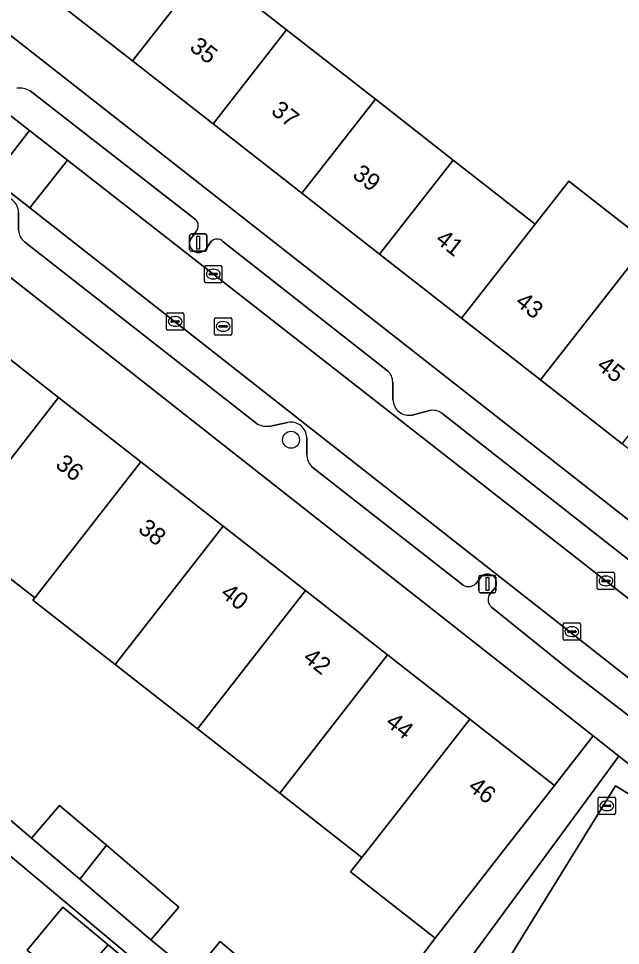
# Model space of a CAD drawing. Extents: x 162803 to 163818, y 381639 to 382475.
# Drawn here: x 163015.6 to 163050.3, y 381895.4 to 381948.9 of the extents above; entities that cross this region are included whole.
import ezdxf

# ---------------------------------------------------------------- set-up
doc = ezdxf.new("R2010")
doc.units = 0
for name, color, linetype in [('IMGEO_Boom', 7, 'Continuous'), ('IMGEO_Erf', 7, 'Continuous'), ('IMGEO_Hek', 7, 'Continuous'), ('IMGEO_Kolk', 7, 'Continuous'), ('IMGEO_Lichtmast', 7, 'Continuous'), ('IMGEO_Pand', 7, 'Continuous'), ('IMGEO_Pand_nummerreeks', 7, 'Continuous'), ('IMGEO_Parkeervlak_open', 7, 'Continuous'), ('IMGEO_Rijbaan_lokaal_open', 7, 'Continuous'), ('IMGEO_Rioolput', 7, 'Continuous'), ('IMGEO_Voetpad_halfverhard', 7, 'Continuous'), ('IMGEO_Voetpad_open', 7, 'Continuous')]:
    doc.layers.add(name, color=color, linetype=linetype)

msp = doc.modelspace()

# ---------------------------------------------------------------- linework, layer by layer
at = {"layer": 'IMGEO_Boom'}
msp.add_circle((163031.306, 381924.552), 0.489, dxfattribs=at)
at = {"layer": 'IMGEO_Erf'}
for points in [[(163012.702, 381953.831), (163008.064, 381957.46), (163003.34, 381961.156), (163000, 381963.77), (162998.624, 381964.847), (162993.983, 381968.479), (162988.995, 381972.382), (162984.262, 381976.085), (162979.885, 381979.51), (162977.939, 381977.029), (163000, 381959.74), (163053.051, 381918.164), (163055.049, 381920.693), (163050.42, 381924.316), (163045.704, 381928.006), (163041.156, 381931.565), (163036.417, 381935.273), (163031.932, 381938.782), (163026.803, 381942.796), (163022.156, 381946.432), (163017.462, 381950.105)], [(163001.097, 381944.923), (162998.748, 381941.944), (163000, 381940.965), (163003.631, 381938.127), (163008.381, 381934.414), (163013.132, 381930.701), (163017.883, 381926.987), (163022.634, 381923.274), (163027.384, 381919.561), (163032.135, 381915.847), (163036.886, 381912.134), (163041.636, 381908.421), (163046.521, 381904.603), (163048.763, 381907.455)], [(163038.651, 381883.086), (163036.828, 381884.162), (163039.676, 381888.972), (163040.229, 381888.673), (163050.041, 381904.572), (163054.928, 381901.596), (163055.361, 381902.269), (163050.243, 381906.292), (163034.914, 381885.439), (163037.605, 381883.275), (163019.349, 381863.218), (163031.785, 381852.208), (163033.858, 381855.537), (163033.587, 381855.698), (163033.798, 381856.014), (163025.478, 381861.115), (163025.295, 381860.793), (163025.018, 381860.951)], [(163018.133, 381897.57), (163020.742, 381895.399), (163024.025, 381892.669), (163021.96, 381890.186), (163018.615, 381892.969), (163016.068, 381895.087)]]:
    msp.add_lwpolyline(points, close=True, dxfattribs=at)
for points in [[(163026.403, 381951.859), (163031.049, 381948.223), (163036.178, 381944.21), (163040.664, 381940.7), (163045.402, 381936.992), (163047.356, 381939.49), (163051.904, 381935.931), (163056.621, 381932.241), (163054.666, 381929.743), (163059.296, 381926.12), (163067.014, 381937.903), (163068.646, 381940.06), (163068.089, 381940.477), (163066.37, 381938.181), (163063.154, 381940.589), (163064.872, 381942.883), (163062.462, 381944.685), (163060.745, 381942.392), (163058, 381944.446), (163053.884, 381947.527), (163055.598, 381949.817)], [(163025.843, 381891.535), (163014.646, 381900.893), (163012.581, 381898.41), (163009.236, 381901.193), (163006.689, 381903.311), (163008.754, 381905.794), (162985.753, 381924.936), (162983.798, 381922.596), (162980.586, 381925.278), (162978.051, 381927.396), (162980.006, 381929.737), (162976.179, 381932.925)], [(163035.802, 381890.676), (163039.628, 381895.786), (163034.743, 381899.605), (163035.402, 381900.447), (163030.653, 381904.16), (163025.903, 381907.874), (163021.151, 381911.588), (163016.4, 381915.301), (163016.507, 381915.438), (163011.757, 381919.152)], [(163013.843, 381903.678), (163016.322, 381901.554), (163017.936, 381903.448), (163020.641, 381901.143), (163024.827, 381897.576), (163023.213, 381895.682), (163025.63, 381893.703), (163027.222, 381895.579), (163029.852, 381893.348)]]:
    msp.add_lwpolyline(points, dxfattribs=at)
at = {"layer": 'IMGEO_Hek'}
msp.add_lwpolyline([(163050.243, 381906.292), (163034.914, 381885.439), (163037.605, 381883.275), (163019.349, 381863.218)], dxfattribs=at)
at = {"layer": 'IMGEO_Kolk'}
for p, q in [((163026.316, 381933.694), (163026.316, 381934.546)), ((163026.391, 381934.62), (163027.243, 381934.62)), ((163027.317, 381934.546), (163027.317, 381933.694)), ((163026.575, 381934.114), (163026.575, 381934.126)), ((163027.013, 381934.077), (163026.615, 381934.077)), ((163026.618, 381934.163), (163027.016, 381934.163)), ((163026.804, 381934.4), (163026.829, 381934.4)), ((163027.059, 381934.126), (163027.059, 381934.114)), ((163027.243, 381933.62), (163026.391, 381933.62)), ((163026.827, 381933.84), (163026.802, 381933.84)), ((163024.182, 381931.883), (163025.034, 381931.883)), ((163024.107, 381930.957), (163024.107, 381931.809)), ((163024.366, 381931.377), (163024.366, 381931.389)), ((163024.804, 381931.34), (163024.406, 381931.34)), ((163024.409, 381931.426), (163024.807, 381931.426)), ((163024.595, 381931.663), (163024.62, 381931.663)), ((163024.85, 381931.389), (163024.85, 381931.377)), ((163025.108, 381931.809), (163025.108, 381930.957)), ((163025.034, 381930.883), (163024.182, 381930.883)), ((163024.618, 381931.103), (163024.593, 381931.103)), ((163049.067, 381916.902), (163049.919, 381916.902)), ((163048.992, 381915.976), (163048.992, 381916.828)), ((163049.251, 381916.396), (163049.251, 381916.408)), ((163049.689, 381916.359), (163049.291, 381916.359)), ((163049.294, 381916.445), (163049.692, 381916.445)), ((163049.48, 381916.682), (163049.505, 381916.682)), ((163049.735, 381916.408), (163049.735, 381916.396)), ((163049.993, 381916.828), (163049.993, 381915.976)), ((163049.919, 381915.902), (163049.067, 381915.902)), ((163049.503, 381916.122), (163049.478, 381916.122)), ((163047.024, 381913.05), (163047.024, 381913.902)), ((163047.099, 381913.976), (163047.951, 381913.976)), ((163047.512, 381913.756), (163047.537, 381913.756)), ((163048.025, 381913.902), (163048.025, 381913.05)), ((163047.283, 381913.47), (163047.283, 381913.482)), ((163047.721, 381913.433), (163047.323, 381913.433)), ((163047.326, 381913.519), (163047.724, 381913.519)), ((163047.535, 381913.196), (163047.51, 381913.196)), ((163047.767, 381913.482), (163047.767, 381913.47)), ((163047.951, 381912.976), (163047.099, 381912.976)), ((163049.038, 381902.997), (163049.038, 381903.849)), ((163049.113, 381903.923), (163049.965, 381903.923)), ((163049.526, 381903.703), (163049.551, 381903.703)), ((163050.039, 381903.849), (163050.039, 381902.997)), ((163049.297, 381903.417), (163049.297, 381903.429)), ((163049.735, 381903.38), (163049.337, 381903.38)), ((163049.34, 381903.466), (163049.738, 381903.466)), ((163049.549, 381903.143), (163049.524, 381903.143)), ((163049.781, 381903.429), (163049.781, 381903.417)), ((163049.965, 381902.923), (163049.113, 381902.923))]:
    msp.add_line(p, q, dxfattribs=at)
for points in [[(163026.316, 381933.694), (163026.316, 381934.546)], [(163026.391, 381934.62), (163027.243, 381934.62)], [(163027.317, 381934.546), (163027.317, 381933.694)], [(163027.243, 381933.62), (163026.391, 381933.62)], [(163024.182, 381931.883), (163025.034, 381931.883)], [(163024.107, 381930.957), (163024.107, 381931.809)], [(163025.108, 381931.809), (163025.108, 381930.957)], [(163025.034, 381930.883), (163024.182, 381930.883)], [(163049.067, 381916.902), (163049.919, 381916.902)], [(163048.992, 381915.976), (163048.992, 381916.828)], [(163049.993, 381916.828), (163049.993, 381915.976)], [(163049.919, 381915.902), (163049.067, 381915.902)], [(163047.024, 381913.05), (163047.024, 381913.902)], [(163047.099, 381913.976), (163047.951, 381913.976)], [(163048.025, 381913.902), (163048.025, 381913.05)], [(163047.951, 381912.976), (163047.099, 381912.976)], [(163049.038, 381902.997), (163049.038, 381903.849)], [(163049.113, 381903.923), (163049.965, 381903.923)], [(163050.039, 381903.849), (163050.039, 381902.997)], [(163049.965, 381902.923), (163049.113, 381902.923)]]:
    msp.add_lwpolyline(points, dxfattribs=at)
for centre, radius, start, end in [((163026.393, 381934.544), 0.0765, 91.552, 178.448), ((163026.393, 381934.544), 0.0765, 91.552, 178.448), ((163027.241, 381934.544), 0.0765, 1.552, 88.448), ((163027.241, 381934.544), 0.0765, 1.552, 88.448), ((163026.615, 381934.123), 0.0403, 85.8775, 175.7526), ((163026.612, 381934.113), 0.0366, 178.938, 274.7102), ((163027.016, 381934.12), 0.043, 264.8664, 352.4533), ((163027.02, 381934.125), 0.0386, 1.7309, 96.639), ((163026.393, 381933.696), 0.0765, 181.552, 268.448), ((163026.393, 381933.696), 0.0765, 181.552, 268.448), ((163027.241, 381933.696), 0.0765, 271.552, 358.448), ((163027.241, 381933.696), 0.0765, 271.552, 358.448), ((163024.184, 381931.807), 0.0765, 91.552, 178.448), ((163024.184, 381931.807), 0.0765, 91.552, 178.448), ((163025.032, 381931.807), 0.0765, 1.552, 88.448), ((163025.032, 381931.807), 0.0765, 1.552, 88.448), ((163024.406, 381931.386), 0.0403, 85.8775, 175.7526), ((163024.403, 381931.376), 0.0366, 178.938, 274.7102), ((163024.807, 381931.383), 0.043, 264.8664, 352.4533), ((163024.811, 381931.388), 0.0386, 1.7309, 96.639), ((163024.184, 381930.959), 0.0765, 181.552, 268.448), ((163024.184, 381930.959), 0.0765, 181.552, 268.448), ((163025.032, 381930.959), 0.0765, 271.552, 358.448), ((163025.032, 381930.959), 0.0765, 271.552, 358.448), ((163049.069, 381916.826), 0.0765, 91.552, 178.448), ((163049.069, 381916.826), 0.0765, 91.552, 178.448), ((163049.917, 381916.826), 0.0765, 1.552, 88.448), ((163049.917, 381916.826), 0.0765, 1.552, 88.448), ((163049.291, 381916.405), 0.0403, 85.8775, 175.7526), ((163049.288, 381916.395), 0.0366, 178.938, 274.7102), ((163049.692, 381916.402), 0.043, 264.8664, 352.4533), ((163049.696, 381916.407), 0.0386, 1.7309, 96.639), ((163049.069, 381915.978), 0.0765, 181.552, 268.448), ((163049.069, 381915.978), 0.0765, 181.552, 268.448), ((163049.917, 381915.978), 0.0765, 271.552, 358.448), ((163049.917, 381915.978), 0.0765, 271.552, 358.448), ((163047.101, 381913.9), 0.0765, 91.552, 178.448), ((163047.101, 381913.9), 0.0765, 91.552, 178.448), ((163047.949, 381913.9), 0.0765, 1.552, 88.448), ((163047.949, 381913.9), 0.0765, 1.552, 88.448), ((163047.323, 381913.479), 0.0403, 85.8775, 175.7526), ((163047.32, 381913.469), 0.0366, 178.938, 274.7102), ((163047.724, 381913.476), 0.043, 264.8664, 352.4533), ((163047.728, 381913.481), 0.0386, 1.7309, 96.639), ((163047.101, 381913.052), 0.0765, 181.552, 268.448), ((163047.101, 381913.052), 0.0765, 181.552, 268.448), ((163047.949, 381913.052), 0.0765, 271.552, 358.448), ((163047.949, 381913.052), 0.0765, 271.552, 358.448), ((163049.115, 381903.847), 0.0765, 91.552, 178.448), ((163049.115, 381903.847), 0.0765, 91.552, 178.448), ((163049.963, 381903.847), 0.0765, 1.552, 88.448), ((163049.963, 381903.847), 0.0765, 1.552, 88.448), ((163049.115, 381902.999), 0.0765, 181.552, 268.448), ((163049.115, 381902.999), 0.0765, 181.552, 268.448), ((163049.337, 381903.426), 0.0403, 85.8775, 175.7526), ((163049.334, 381903.416), 0.0366, 178.938, 274.7102), ((163049.738, 381903.423), 0.043, 264.8664, 352.4533), ((163049.742, 381903.428), 0.0386, 1.7309, 96.639), ((163049.963, 381902.999), 0.0765, 271.552, 358.448), ((163049.963, 381902.999), 0.0765, 271.552, 358.448)]:
    msp.add_arc(centre, radius, start, end, dxfattribs=at)
for centre, major_axis, ratio, start_param, end_param in [((163026.803, 381934.12), (-0.387, 0.002), 0.722429, 4.712389, 7.853982), ((163026.828, 381934.12), (-0.39, 0.002), 0.717154, 1.570796, 4.712389), ((163024.594, 381931.383), (-0.387, 0.002), 0.722429, 4.712389, 7.853982), ((163024.619, 381931.383), (-0.39, 0.002), 0.717154, 1.570796, 4.712389), ((163049.479, 381916.402), (-0.387, 0.002), 0.722429, 4.712389, 7.853982), ((163049.504, 381916.402), (-0.39, 0.002), 0.717154, 1.570796, 4.712389), ((163047.511, 381913.476), (-0.387, 0.002), 0.722429, 4.712389, 7.853982), ((163047.536, 381913.476), (-0.39, 0.002), 0.717154, 1.570796, 4.712389), ((163049.525, 381903.423), (-0.387, 0.002), 0.722429, 4.712389, 7.853982), ((163049.55, 381903.423), (-0.39, 0.002), 0.717154, 1.570796, 4.712389)]:
    msp.add_ellipse(centre, major_axis=major_axis, ratio=ratio, start_param=start_param, end_param=end_param, dxfattribs=at)
at = {"layer": 'IMGEO_Lichtmast'}
for p, q in [((163025.449, 381935.539), (163025.449, 381936.339)), ((163025.449, 381936.339), (163025.449, 381935.539)), ((163025.549, 381936.439), (163026.339, 381936.439)), ((163026.339, 381936.439), (163025.549, 381936.439)), ((163026.439, 381936.339), (163026.439, 381935.539)), ((163026.439, 381935.539), (163026.439, 381936.339)), ((163026.339, 381935.439), (163025.549, 381935.439)), ((163025.549, 381935.439), (163026.339, 381935.439)), ((163042.151, 381915.824), (163042.151, 381916.624)), ((163042.151, 381916.624), (163042.151, 381915.824)), ((163042.251, 381916.724), (163043.041, 381916.724)), ((163043.041, 381916.724), (163042.251, 381916.724)), ((163043.141, 381916.624), (163043.141, 381915.824)), ((163043.141, 381915.824), (163043.141, 381916.624)), ((163043.041, 381915.724), (163042.251, 381915.724)), ((163042.251, 381915.724), (163043.041, 381915.724))]:
    msp.add_line(p, q, dxfattribs=at)
for points in [[(163025.869, 381936.314), (163026.019, 381936.314), (163026.019, 381935.564), (163025.869, 381935.564), (163025.869, 381936.314)], [(163042.571, 381916.599), (163042.721, 381916.599), (163042.721, 381915.849), (163042.571, 381915.849), (163042.571, 381916.599)]]:
    msp.add_lwpolyline(points, dxfattribs=at)
for centre, start, end in [((163025.549, 381936.339), 90, 180), ((163025.549, 381936.339), 90, 180), ((163026.339, 381936.339), 0, 90), ((163026.339, 381936.339), 360, 90), ((163025.549, 381935.539), 180, 270), ((163025.549, 381935.539), 180, 270), ((163026.339, 381935.539), 270, 0), ((163026.339, 381935.539), 270, 0), ((163042.251, 381916.624), 90, 180), ((163042.251, 381916.624), 90, 180), ((163043.041, 381916.624), 0, 90), ((163043.041, 381916.624), 360, 90), ((163042.251, 381915.824), 180, 270), ((163042.251, 381915.824), 180, 270), ((163043.041, 381915.824), 270, 0), ((163043.041, 381915.824), 270, 0)]:
    msp.add_arc(centre, 0.1, start, end, dxfattribs=at)
at = {"layer": 'IMGEO_Pand'}
for points in [[(163021.709, 381955.532), (163017.462, 381950.105), (163022.156, 381946.432), (163026.403, 381951.859), (163028.356, 381954.355), (163023.662, 381958.028)], [(163031.049, 381948.223), (163026.403, 381951.859), (163022.156, 381946.432), (163026.803, 381942.796)], [(163031.932, 381938.782), (163036.178, 381944.21), (163031.049, 381948.223), (163026.803, 381942.796)], [(163036.417, 381935.273), (163040.664, 381940.7), (163036.178, 381944.21), (163031.932, 381938.782)], [(163036.417, 381935.273), (163041.156, 381931.565), (163045.402, 381936.992), (163040.664, 381940.7)], [(163045.704, 381928.006), (163051.904, 381935.931), (163047.356, 381939.49), (163045.402, 381936.992), (163041.156, 381931.565)], [(163054.666, 381929.743), (163056.621, 381932.241), (163051.904, 381935.931), (163045.704, 381928.006), (163050.42, 381924.316)], [(163017.883, 381926.987), (163013.132, 381930.701), (163008.56, 381924.853), (163013.311, 381921.14)], [(163022.634, 381923.274), (163017.883, 381926.987), (163013.311, 381921.14), (163011.757, 381919.152), (163016.507, 381915.438), (163018.062, 381917.427)], [(163027.384, 381919.561), (163022.634, 381923.274), (163018.062, 381917.427), (163016.507, 381915.438), (163016.4, 381915.301), (163021.151, 381911.588)], [(163025.903, 381907.874), (163032.135, 381915.847), (163027.384, 381919.561), (163021.151, 381911.588)], [(163030.653, 381904.16), (163036.886, 381912.134), (163032.135, 381915.847), (163025.903, 381907.874)], [(163030.653, 381904.16), (163035.402, 381900.447), (163037.065, 381902.574), (163041.636, 381908.421), (163036.886, 381912.134)], [(163041.636, 381908.421), (163037.065, 381902.574), (163035.402, 381900.447), (163034.743, 381899.605), (163039.628, 381895.786), (163041.95, 381898.756), (163043.442, 381900.664), (163046.521, 381904.603)], [(163020.641, 381901.143), (163017.936, 381903.448), (163016.322, 381901.554), (163019.108, 381899.18)], [(163020.641, 381901.143), (163019.108, 381899.18), (163023.213, 381895.682), (163024.827, 381897.576)], [(163018.615, 381892.969), (163020.742, 381895.399), (163018.133, 381897.57), (163016.068, 381895.087)], [(163029.852, 381893.348), (163027.222, 381895.579), (163025.63, 381893.703), (163028.335, 381891.407)], [(163018.615, 381892.969), (163021.96, 381890.186), (163024.025, 381892.669), (163020.742, 381895.399)]]:
    msp.add_lwpolyline(points, close=True, dxfattribs=at)
at = {"layer": 'IMGEO_Parkeervlak_open'}
for points in [[(162916.457, 382020.33), (162920.977, 382016.827), (162934.305, 382006.499), (162942.597, 382000), (162953.262, 381991.64), (162955.442, 381989.931), (162973.286, 381975.945), (163000, 381955.072), (163016.211, 381942.406), (163018.389, 381940.704), (163067.037, 381902.692)], [(163054.221, 381908.123), (163016.226, 381937.935), (163014.048, 381939.637), (163000, 381950.614), (162953.337, 381987.077)], [(163025.782, 381937.279), (163016.231, 381944.693)], [(163015.568, 381937.676), (163015.57, 381936.66)], [(163025.516, 381936.157), (163025.813, 381936.563)], [(163015.912, 381935.982), (163029.377, 381925.454)], [(163026.673, 381935.977), (163026.396, 381935.569)], [(163036.873, 381928.536), (163027.376, 381935.999)], [(163037.192, 381926.86), (163037.178, 381927.872)], [(163039.312, 381926.235), (163038.309, 381925.982)], [(163053.502, 381915.504), (163040.014, 381926.083)], [(163030.116, 381925.338), (163031.109, 381925.56)], [(163032.218, 381924.682), (163032.211, 381923.696)], [(163032.512, 381922.995), (163041.243, 381916.167)], [(163041.975, 381916.246), (163042.28, 381916.632)], [(163043.082, 381915.982), (163042.737, 381915.571)], [(163042.877, 381914.896), (163047.545, 381911.134), (163051.493, 381908.094)]]:
    msp.add_lwpolyline(points, dxfattribs=at)
msp.add_lwpolyline([(163054.928, 381901.596), (163050.041, 381904.572), (163040.229, 381888.673), (163039.676, 381888.972), (163036.828, 381884.162), (163038.651, 381883.086), (163047.476, 381877.66), (163047.942, 381878.433), (163047.993, 381878.397), (163052.886, 381886.336), (163054.736, 381885.241), (163060.471, 381894.547), (163058.635, 381895.702), (163060.268, 381898.298)], close=True, dxfattribs=at)
for centre, radius, start, end in [((163015.623, 381943.671), 1.19, 59.244, 97.5606), ((163014.64, 381937.667), 0.928, 0.5365, 101.0147), ((163025.447, 381936.906), 0.501, 316.8705, 48.0878), ((163016.482, 381936.695), 0.913, 182.1822, 231.3528), ((163025.975, 381935.892), 0.53, 150.0331, 322.4667), ((163027.035, 381935.661), 0.481, 44.7501, 138.8348), ((163036.335, 381927.887), 0.844, 359.0078, 50.3344), ((163038.128, 381926.902), 0.937, 182.5581, 281.1048), ((163039.505, 381925.428), 0.829, 52.1242, 103.4411), ((163029.957, 381926.738), 1.409, 245.6827, 276.4756), ((163031.282, 381924.639), 0.937, 2.6466, 100.6158), ((163033.212, 381923.711), 1.001, 180.8459, 225.6302), ((163042.664, 381916.287), 0.517, 323.8908, 138.0614), ((163041.559, 381916.673), 0.596, 238.0161, 314.3033), ((163043.254, 381915.326), 0.572, 154.691, 228.7439)]:
    msp.add_arc(centre, radius, start, end, dxfattribs=at)
at = {"layer": 'IMGEO_Rijbaan_lokaal_open'}
for points in [[(163014.048, 381939.637), (163016.211, 381942.406), (163000, 381955.072), (162973.286, 381975.945), (162955.442, 381989.931), (162953.337, 381987.077), (163000, 381950.614)], [(163016.226, 381937.935), (163018.389, 381940.704), (163016.211, 381942.406), (163014.048, 381939.637)], [(163018.389, 381940.704), (163016.226, 381937.935), (163054.221, 381908.123), (163058.977, 381904.423), (163067.173, 381897.988), (163069.543, 381896.09), (163071.739, 381898.909), (163069.313, 381900.831), (163067.037, 381902.692)]]:
    msp.add_lwpolyline(points, close=True, dxfattribs=at)
at = {"layer": 'IMGEO_Rioolput'}
for p, q in [((163026.885, 381930.672), (163026.885, 381931.524)), ((163026.96, 381931.598), (163027.812, 381931.598)), ((163027.373, 381931.378), (163027.398, 381931.378)), ((163027.886, 381931.524), (163027.886, 381930.672)), ((163027.144, 381931.092), (163027.144, 381931.104)), ((163027.582, 381931.055), (163027.184, 381931.055)), ((163027.187, 381931.141), (163027.585, 381931.141)), ((163027.396, 381930.818), (163027.371, 381930.818)), ((163027.628, 381931.104), (163027.628, 381931.092)), ((163027.812, 381930.598), (163026.96, 381930.598))]:
    msp.add_line(p, q, dxfattribs=at)
for points in [[(163026.885, 381930.672), (163026.885, 381931.524)], [(163026.96, 381931.598), (163027.812, 381931.598)], [(163027.886, 381931.524), (163027.886, 381930.672)], [(163027.812, 381930.598), (163026.96, 381930.598)]]:
    msp.add_lwpolyline(points, dxfattribs=at)
for centre, radius, start, end in [((163026.962, 381931.522), 0.0765, 91.552, 178.448), ((163026.962, 381931.522), 0.0765, 91.552, 178.448), ((163027.81, 381931.522), 0.0765, 1.552, 88.448), ((163027.81, 381931.522), 0.0765, 1.552, 88.448), ((163027.184, 381931.101), 0.0403, 85.8775, 175.7526), ((163027.181, 381931.091), 0.0366, 178.938, 274.7102), ((163027.585, 381931.098), 0.043, 264.8664, 352.4533), ((163027.589, 381931.103), 0.0386, 1.7309, 96.639), ((163026.962, 381930.674), 0.0765, 181.552, 268.448), ((163026.962, 381930.674), 0.0765, 181.552, 268.448), ((163027.81, 381930.674), 0.0765, 271.552, 358.448), ((163027.81, 381930.674), 0.0765, 271.552, 358.448)]:
    msp.add_arc(centre, radius, start, end, dxfattribs=at)
for centre, major_axis, ratio, start_param, end_param in [((163027.372, 381931.098), (-0.387, 0.002), 0.722429, 4.712389, 7.853982), ((163027.397, 381931.098), (-0.39, 0.002), 0.717154, 1.570796, 4.712389)]:
    msp.add_ellipse(centre, major_axis=major_axis, ratio=ratio, start_param=start_param, end_param=end_param, dxfattribs=at)
at = {"layer": 'IMGEO_Voetpad_halfverhard'}
for points in [[(163025.63, 381893.703), (163023.213, 381895.682), (163019.108, 381899.18), (163016.322, 381901.554), (163013.843, 381903.678), (163009.914, 381906.867), (163009.092, 381907.391), (163005.163, 381910.58), (163004.136, 381911.37), (163000.469, 381914.504), (162996.921, 381917.538), (162994.856, 381919.113), (162991.203, 381922.236), (162987.642, 381925.281), (162985.806, 381926.851), (162993.662, 381936.483), (162994.178, 381936.095), (162995.67, 381938.005), (162998.748, 381941.944), (163001.097, 381944.923), (162999.395, 381946.261), (162991.322, 381936.036), (162984.705, 381927.78), (162979.07, 381932.405)], [(162976.179, 381932.925), (162980.006, 381929.737), (162982.596, 381927.574), (162985.753, 381924.936), (163008.754, 381905.794), (163011.364, 381903.623), (163014.646, 381900.893), (163025.843, 381891.535)], [(163034.914, 381885.439), (163050.243, 381906.292), (163048.763, 381907.455), (163046.521, 381904.603), (163043.442, 381900.664), (163041.95, 381898.756), (163039.628, 381895.786), (163035.802, 381890.676)]]:
    msp.add_lwpolyline(points, dxfattribs=at)
at = {"layer": 'IMGEO_Voetpad_open'}
for points in [[(162926.547, 382003.598), (162928.941, 382001.641), (162955.144, 381981.044), (162956.756, 381979.777), (162998.706, 381946.802), (162999.395, 381946.261), (163001.097, 381944.923), (163048.763, 381907.455), (163050.243, 381906.292), (163055.361, 381902.269), (163054.928, 381901.596), (163060.268, 381898.298), (163068.177, 381892.47), (163068.653, 381891.896), (163070.942, 381894.943), (163069.543, 381896.09), (163067.173, 381897.988), (163058.977, 381904.423), (163054.221, 381908.123)], [(163072.436, 381902.972), (163054.275, 381917.204), (163053.051, 381918.164), (163000, 381959.74)], [(163016.231, 381944.693), (163025.782, 381937.279)], [(163015.57, 381936.66), (163015.568, 381937.676)], [(163025.813, 381936.563), (163025.516, 381936.157)], [(163029.377, 381925.454), (163015.912, 381935.982)], [(163026.396, 381935.569), (163026.673, 381935.977)], [(163027.376, 381935.999), (163036.873, 381928.536)], [(163037.178, 381927.872), (163037.192, 381926.86)], [(163038.309, 381925.982), (163039.312, 381926.235)], [(163040.014, 381926.083), (163053.502, 381915.504)], [(163031.109, 381925.56), (163030.116, 381925.338)], [(163032.211, 381923.696), (163032.218, 381924.682)], [(163041.243, 381916.167), (163032.512, 381922.995)], [(163042.28, 381916.632), (163041.975, 381916.246)], [(163042.737, 381915.571), (163043.082, 381915.982)], [(163051.493, 381908.094), (163047.545, 381911.134), (163042.877, 381914.896)]]:
    msp.add_lwpolyline(points, dxfattribs=at)
for centre, radius, start, end in [((163015.623, 381943.671), 1.19, 59.244, 97.5606), ((163014.64, 381937.667), 0.928, 0.5365, 101.0147), ((163025.447, 381936.906), 0.501, 316.8705, 48.0878), ((163016.482, 381936.695), 0.913, 182.1822, 231.3528), ((163025.975, 381935.892), 0.53, 150.0331, 322.4667), ((163027.035, 381935.661), 0.481, 44.7501, 138.8348), ((163036.335, 381927.887), 0.844, 359.0078, 50.3344), ((163038.128, 381926.902), 0.937, 182.5581, 281.1048), ((163039.505, 381925.428), 0.829, 52.1242, 103.4411), ((163029.957, 381926.738), 1.409, 245.6827, 276.4756), ((163031.282, 381924.639), 0.937, 2.6466, 100.6158), ((163033.212, 381923.711), 1.001, 180.8459, 225.6302), ((163042.664, 381916.287), 0.517, 323.8908, 138.0614), ((163041.559, 381916.673), 0.596, 238.0161, 314.3033), ((163043.254, 381915.326), 0.572, 154.691, 228.7439)]:
    msp.add_arc(centre, radius, start, end, dxfattribs=at)

# ---------------------------------------------------------------- texts
at = {"layer": 'IMGEO_Pand_nummerreeks'}
for s, rotation, p in [('35', 321.9561, (163025.387, 381947.104)), ('37', 321.9561, (163030.09, 381943.424)), ('39', 321.9561, (163034.792, 381939.745)), ('41', 321.9561, (163039.583, 381935.995)), ('43', 321.9561, (163044.196, 381932.386)), ('45', 321.9561, (163048.898, 381928.706)), ('36', 321.99, (163017.639, 381923.014)), ('38', 321.99, (163022.408, 381919.287)), ('40', 321.9879, (163027.173, 381915.563)), ('42', 321.9879, (163031.933, 381911.842)), ('44', 321.9879, (163036.701, 381908.116)), ('46', 321.9879, (163041.466, 381904.391))]:
    msp.add_text(s, height=1, rotation=rotation, dxfattribs=at).set_placement(p)

doc.saveas('drawing.dxf')
